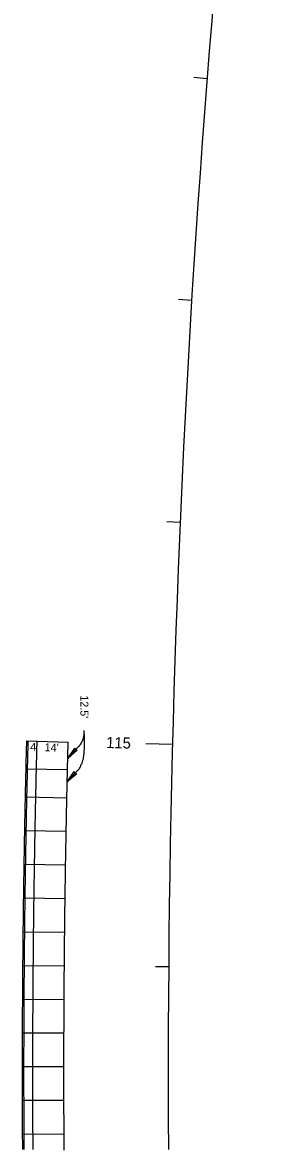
# Model space of a CAD drawing. Extents: x 2145147 to 2158018, y 137519 to 148068.
# Drawn here: x 2150739 to 2150856, y 146337 to 146844 of the extents above; entities that cross this region are included whole.
import ezdxf

# ---------------------------------------------------------------- set-up
doc = ezdxf.new("R2010")
doc.units = 0
for name, color, linetype in [('EX_Align', 7, 'Continuous'), ('EX_Align_Sta', 7, 'Continuous'), ('PR_Dimensions', 7, 'Continuous'), ('PR_Joint_Contraction', 7, 'Continuous'), ('PR_Joint_Long', 7, 'Continuous'), ('PR_Road_Concrete', 7, 'Continuous')]:
    doc.layers.add(name, color=color, linetype=linetype)

msp = doc.modelspace()

# ---------------------------------------------------------------- linework, layer by layer
at = {"layer": 'EX_Align'}
for points in [[(2150816.02, 146819.16), (2150822, 146818.69)], [(2150809.07, 146719.3), (2150815.06, 146718.94)], [(2150803.87, 146619.33), (2150809.87, 146619.07)], [(2150794.42, 146519.44), (2150806.41, 146519.13)], [(2150798.7, 146419.2), (2150804.7, 146419.15)]]:
    msp.add_lwpolyline(points, dxfattribs=at)
msp.add_arc((2156534.08, 146371.27), 5729.58, 162.772825, 180.344259, dxfattribs=at)
at = {"layer": 'PR_Dimensions'}
for points in [[(2150759.24, 146512.79), (2150762.39, 146517.43), (2150762.56, 146516.5), (2150763.53, 146516.41)], [(2150758.99, 146502.2), (2150762.14, 146506.85), (2150762.31, 146505.92), (2150763.28, 146505.82)]]:
    msp.add_lwpolyline(points, close=True, dxfattribs=at)
for points in [[(2150766.51, 146525.33), (2150766.94, 146514.1), (2150764.48, 146508.01), (2150763.54, 146507.3), (2150758.99, 146502.2)], [(2150766.51, 146525.33), (2150766.6, 146522.27), (2150764.73, 146518.59), (2150763.79, 146517.88), (2150759.24, 146512.79)]]:
    msp.add_open_spline(points, degree=2, dxfattribs=at)
at = {"layer": 'PR_Joint_Contraction'}
for p, q in [((2150740.45, 146508.14), (2150759.12, 146507.7)), ((2150740.17, 146495.5), (2150758.83, 146495.1)), ((2150739.86, 146480.33), (2150758.53, 146479.98)), ((2150739.6, 146465.16), (2150758.26, 146464.86)), ((2150739.37, 146449.99), (2150758.04, 146449.74)), ((2150739.19, 146434.82), (2150757.85, 146434.61)), ((2150739.04, 146419.65), (2150757.71, 146419.49)), ((2150738.93, 146404.48), (2150757.6, 146404.37)), ((2150738.87, 146389.3), (2150757.53, 146389.25)), ((2150738.84, 146374.13), (2150757.5, 146374.12)), ((2150738.85, 146358.96), (2150757.52, 146359)), ((2150738.9, 146343.79), (2150757.57, 146343.88))]:
    msp.add_line(p, q, dxfattribs=at)
at = {"layer": 'PR_Joint_Long'}
for points in [[(2150743.61, 146336.79), (2150743.6, 146337.8), (2150743.6, 146338.81), (2150743.59, 146339.82), (2150743.58, 146340.83), (2150743.58, 146341.84), (2150743.57, 146342.85), (2150743.57, 146342.87), (2150743.57, 146343.86), (2150743.56, 146344.87), (2150743.56, 146345.88), (2150743.56, 146346.89), (2150743.55, 146347.9), (2150743.55, 146348.92), (2150743.54, 146349.93), (2150743.54, 146350.94), (2150743.54, 146351.79), (2150743.54, 146351.95), (2150743.53, 146352.96), (2150743.53, 146353.97), (2150743.53, 146354.98), (2150743.52, 146355.99), (2150743.52, 146357), (2150743.52, 146358.01), (2150743.52, 146359.02), (2150743.52, 146360.03), (2150743.51, 146361.04), (2150743.51, 146362.05), (2150743.51, 146363.06), (2150743.51, 146364.07), (2150743.51, 146365.09), (2150743.51, 146366.1), (2150743.51, 146366.5), (2150743.51, 146367.11), (2150743.51, 146368.12), (2150743.5, 146369.13), (2150743.5, 146370.14), (2150743.5, 146371.15), (2150743.5, 146372.16), (2150743.5, 146373.17), (2150743.5, 146374.18), (2150743.51, 146374.97), (2150743.51, 146375.19), (2150743.51, 146376.2), (2150743.51, 146376.23), (2150743.51, 146377.21), (2150743.51, 146378.22), (2150743.51, 146379.23), (2150743.51, 146380.25), (2150743.51, 146381.26), (2150743.51, 146382.27), (2150743.51, 146382.4), (2150743.52, 146383.28), (2150743.52, 146384.29), (2150743.52, 146385.02), (2150743.52, 146385.3), (2150743.52, 146386.31), (2150743.53, 146387.32), (2150743.53, 146388.33), (2150743.53, 146389.34), (2150743.54, 146390.35), (2150743.54, 146391.36), (2150743.54, 146392.37), (2150743.55, 146393.38), (2150743.55, 146394.39), (2150743.55, 146395.4), (2150743.56, 146396.42), (2150743.56, 146397.43), (2150743.56, 146397.71), (2150743.57, 146398.44), (2150743.57, 146399.45), (2150743.58, 146400.46), (2150743.58, 146401.47), (2150743.59, 146402.48), (2150743.59, 146403.49), (2150743.6, 146404.5), (2150743.61, 146405.51), (2150743.61, 146406.52), (2150743.62, 146407.53), (2150743.62, 146408.54), (2150743.63, 146409.55), (2150743.64, 146410.56), (2150743.64, 146411.57), (2150743.65, 146412.59), (2150743.65, 146413.02), (2150743.66, 146413.6), (2150743.67, 146414.61), (2150743.67, 146415.62), (2150743.68, 146416.63), (2150743.69, 146417.64), (2150743.7, 146418.65), (2150743.71, 146419.66), (2150743.72, 146420.67), (2150743.72, 146421.68), (2150743.73, 146422.69), (2150743.74, 146423.7), (2150743.75, 146424.71), (2150743.76, 146425.72), (2150743.77, 146426.73), (2150743.78, 146427.74), (2150743.79, 146428.33), (2150743.79, 146428.76), (2150743.8, 146429.77), (2150743.81, 146430.78), (2150743.82, 146431.79), (2150743.83, 146432.8), (2150743.84, 146433.81), (2150743.85, 146434.82), (2150743.86, 146435.83), (2150743.88, 146436.84), (2150743.89, 146437.85), (2150743.9, 146438.86), (2150743.91, 146439.87), (2150743.92, 146440.88), (2150743.93, 146441.89), (2150743.95, 146442.9), (2150743.96, 146443.64), (2150743.96, 146443.91), (2150743.97, 146444.72), (2150743.97, 146444.92), (2150743.99, 146445.94), (2150744, 146446.95), (2150744.01, 146447.96), (2150744.03, 146448.97), (2150744.04, 146449.98), (2150744.05, 146450.99), (2150744.07, 146452), (2150744.08, 146453.01), (2150744.1, 146454.02), (2150744.11, 146455.03), (2150744.12, 146456.04), (2150744.14, 146457.05), (2150744.15, 146458.06), (2150744.17, 146458.95), (2150744.17, 146459.07), (2150744.19, 146460.08), (2150744.2, 146461.09), (2150744.22, 146462.1), (2150744.23, 146463.11), (2150744.25, 146464.12), (2150744.27, 146465.14), (2150744.28, 146466.15), (2150744.28, 146466.33), (2150744.3, 146467.16), (2150744.32, 146468.17), (2150744.33, 146469.18), (2150744.35, 146470.19), (2150744.37, 146471.2), (2150744.38, 146472.21), (2150744.4, 146473.22), (2150744.42, 146474.23), (2150744.42, 146474.25), (2150744.44, 146475.24), (2150744.46, 146476.25), (2150744.47, 146477.26), (2150744.49, 146478.27), (2150744.51, 146479.28), (2150744.53, 146480.29), (2150744.55, 146481.3), (2150744.57, 146482.31), (2150744.59, 146483.32), (2150744.61, 146484.33), (2150744.63, 146485.35), (2150744.65, 146486.36), (2150744.67, 146487.37), (2150744.69, 146488.38), (2150744.71, 146489.39), (2150744.71, 146489.56), (2150744.73, 146490.4), (2150744.75, 146491.41), (2150744.76, 146491.89), (2150744.77, 146492.42), (2150744.79, 146493.43), (2150744.81, 146494.44), (2150744.84, 146495.45), (2150744.86, 146496.46), (2150744.88, 146497.47), (2150744.9, 146498.48), (2150744.92, 146499.49), (2150744.95, 146500.5), (2150744.97, 146501.51), (2150744.99, 146502.52), (2150745.01, 146503.53), (2150745.04, 146504.54), (2150745.05, 146504.86), (2150745.06, 146505.55), (2150745.09, 146506.56), (2150745.11, 146507.49), (2150745.11, 146507.57), (2150745.13, 146508.58), (2150745.16, 146509.59), (2150745.18, 146510.61), (2150745.21, 146511.62), (2150745.23, 146512.63), (2150745.25, 146513.64), (2150745.28, 146514.65), (2150745.3, 146515.66), (2150745.33, 146516.67), (2150745.36, 146517.68), (2150745.38, 146518.69), (2150745.41, 146519.7), (2150745.42, 146520.17), (2150745.43, 146520.49)], [(2150757.61, 146336.56), (2150757.61, 146336.87), (2150757.6, 146337.88), (2150757.6, 146338.89), (2150757.59, 146339.9), (2150757.58, 146340.9), (2150757.58, 146341.91), (2150757.57, 146342.92), (2150757.57, 146342.94), (2150757.57, 146343.93), (2150757.56, 146344.94), (2150757.56, 146345.94), (2150757.56, 146346.95), (2150757.55, 146347.96), (2150757.55, 146348.97), (2150757.54, 146349.98), (2150757.54, 146350.99), (2150757.54, 146351.83), (2150757.54, 146351.99), (2150757.53, 146353), (2150757.53, 146354.01), (2150757.53, 146355.02), (2150757.52, 146356.03), (2150757.52, 146357.03), (2150757.52, 146358.04), (2150757.52, 146359.05), (2150757.52, 146360.06), (2150757.51, 146361.07), (2150757.51, 146362.08), (2150757.51, 146363.08), (2150757.51, 146364.09), (2150757.51, 146365.1), (2150757.51, 146366.11), (2150757.51, 146366.51), (2150757.51, 146367.1), (2150757.51, 146367.12), (2150757.51, 146368.13), (2150757.5, 146369.13), (2150757.5, 146370.14), (2150757.5, 146371.15), (2150757.5, 146372.16), (2150757.5, 146373.17), (2150757.5, 146374.17), (2150757.51, 146374.96), (2150757.51, 146375.18), (2150757.51, 146376.19), (2150757.51, 146376.22), (2150757.51, 146377.2), (2150757.51, 146378.21), (2150757.51, 146379.22), (2150757.51, 146380.22), (2150757.51, 146381.23), (2150757.51, 146382.24), (2150757.51, 146382.38), (2150757.52, 146383.25), (2150757.52, 146384.26), (2150757.52, 146384.99), (2150757.52, 146385.26), (2150757.52, 146386.27), (2150757.53, 146387.28), (2150757.53, 146388.29), (2150757.53, 146389.3), (2150757.54, 146390.31), (2150757.54, 146391.31), (2150757.54, 146392.32), (2150757.55, 146393.33), (2150757.55, 146394.34), (2150757.55, 146395.35), (2150757.56, 146396.35), (2150757.56, 146397.36), (2150757.56, 146397.65), (2150757.57, 146398.37), (2150757.57, 146399.38), (2150757.58, 146400.39), (2150757.58, 146401.4), (2150757.59, 146402.4), (2150757.59, 146403.41), (2150757.6, 146404.42), (2150757.61, 146405.43), (2150757.61, 146406.44), (2150757.62, 146407.43), (2150757.62, 146407.44), (2150757.62, 146408.45), (2150757.63, 146409.46), (2150757.64, 146410.47), (2150757.64, 146411.48), (2150757.65, 146412.49), (2150757.65, 146412.92), (2150757.66, 146413.49), (2150757.67, 146414.5), (2150757.67, 146415.51), (2150757.68, 146416.52), (2150757.69, 146417.53), (2150757.7, 146418.53), (2150757.71, 146419.54), (2150757.71, 146420.55), (2150757.72, 146421.56), (2150757.73, 146422.57), (2150757.74, 146423.58), (2150757.75, 146424.58), (2150757.76, 146425.59), (2150757.77, 146426.6), (2150757.78, 146427.61), (2150757.78, 146428.19), (2150757.79, 146428.62), (2150757.8, 146429.62), (2150757.81, 146430.63), (2150757.82, 146431.64), (2150757.83, 146432.65), (2150757.84, 146433.66), (2150757.85, 146434.67), (2150757.86, 146435.67), (2150757.87, 146436.68), (2150757.89, 146437.69), (2150757.9, 146438.7), (2150757.91, 146439.71), (2150757.92, 146440.71), (2150757.93, 146441.72), (2150757.95, 146442.73), (2150757.96, 146443.46), (2150757.96, 146443.74), (2150757.97, 146444.55), (2150757.97, 146444.75), (2150757.98, 146445.75), (2150758, 146446.76), (2150758.01, 146447.77), (2150758.02, 146448.78), (2150758.04, 146449.79), (2150758.05, 146450.8), (2150758.07, 146451.8), (2150758.08, 146452.81), (2150758.09, 146453.82), (2150758.11, 146454.83), (2150758.12, 146455.84), (2150758.14, 146456.84), (2150758.15, 146457.85), (2150758.17, 146458.73), (2150758.17, 146458.86), (2150758.18, 146459.87), (2150758.2, 146460.88), (2150758.22, 146461.88), (2150758.23, 146462.89), (2150758.25, 146463.9), (2150758.26, 146464.91), (2150758.28, 146465.92), (2150758.28, 146466.1), (2150758.3, 146466.92), (2150758.31, 146467.93), (2150758.33, 146468.94), (2150758.35, 146469.95), (2150758.36, 146470.96), (2150758.38, 146471.96), (2150758.4, 146472.97), (2150758.42, 146473.98), (2150758.42, 146474), (2150758.44, 146474.99), (2150758.45, 146476), (2150758.47, 146477.01), (2150758.49, 146478.01), (2150758.51, 146479.02), (2150758.53, 146480.03), (2150758.55, 146481.04), (2150758.57, 146482.05), (2150758.59, 146483.05), (2150758.61, 146484.06), (2150758.63, 146485.07), (2150758.65, 146486.08), (2150758.67, 146487.09), (2150758.69, 146488.09), (2150758.71, 146489.1), (2150758.71, 146489.27), (2150758.73, 146490.11), (2150758.75, 146491.12), (2150758.76, 146491.6), (2150758.77, 146492.13), (2150758.79, 146493.13), (2150758.81, 146494.14), (2150758.83, 146495.15), (2150758.85, 146496.16), (2150758.88, 146497.17), (2150758.9, 146498.17), (2150758.92, 146499.18), (2150758.94, 146500.19), (2150758.97, 146501.2), (2150758.99, 146502.2), (2150759.01, 146503.21), (2150759.03, 146504.22), (2150759.04, 146504.54), (2150759.06, 146505.23), (2150759.08, 146506.24), (2150759.1, 146507.16), (2150759.1, 146507.24), (2150759.13, 146508.25), (2150759.15, 146509.26), (2150759.18, 146510.27), (2150759.2, 146511.28), (2150759.23, 146512.28), (2150759.25, 146513.29), (2150759.28, 146514.3), (2150759.3, 146515.31), (2150759.33, 146516.32), (2150759.35, 146517.32), (2150759.38, 146518.33), (2150759.4, 146519.34), (2150759.41, 146519.81), (2150759.42, 146520.13)]]:
    msp.add_lwpolyline(points, dxfattribs=at)
at = {"layer": 'PR_Road_Concrete'}
msp.add_line((2150740.76, 146520.61), (2150759.42, 146520.13), dxfattribs=at)
for points in [[(2150738.94, 146336.76), (2150738.93, 146337.77), (2150738.93, 146338.78), (2150738.92, 146339.79), (2150738.92, 146340.81), (2150738.91, 146341.82), (2150738.91, 146342.83), (2150738.91, 146342.85), (2150738.9, 146343.84), (2150738.9, 146344.85), (2150738.89, 146345.86), (2150738.89, 146346.87), (2150738.88, 146347.89), (2150738.88, 146348.9), (2150738.88, 146349.91), (2150738.87, 146350.92), (2150738.87, 146351.77), (2150738.87, 146351.93), (2150738.87, 146352.94), (2150738.86, 146353.95), (2150738.86, 146354.97), (2150738.86, 146355.98), (2150738.86, 146356.99), (2150738.85, 146358), (2150738.85, 146359.01), (2150738.85, 146360.02), (2150738.85, 146361.03), (2150738.84, 146362.05), (2150738.84, 146363.06), (2150738.84, 146364.07), (2150738.84, 146365.08), (2150738.84, 146366.09), (2150738.84, 146366.49), (2150738.84, 146367.09), (2150738.84, 146367.1), (2150738.84, 146368.11), (2150738.84, 146369.13), (2150738.84, 146370.14), (2150738.84, 146371.15), (2150738.84, 146372.16), (2150738.84, 146373.17), (2150738.84, 146374.18), (2150738.84, 146374.97), (2150738.84, 146375.2), (2150738.84, 146376.21), (2150738.84, 146376.24), (2150738.84, 146377.22), (2150738.84, 146378.23), (2150738.84, 146379.24), (2150738.84, 146380.25), (2150738.85, 146381.26), (2150738.85, 146382.28), (2150738.85, 146382.41), (2150738.85, 146383.29), (2150738.85, 146384.3), (2150738.85, 146385.03), (2150738.85, 146385.31), (2150738.86, 146386.32), (2150738.86, 146387.33), (2150738.86, 146388.34), (2150738.87, 146389.36), (2150738.87, 146390.37), (2150738.87, 146391.38), (2150738.88, 146392.39), (2150738.88, 146393.4), (2150738.88, 146394.41), (2150738.89, 146395.42), (2150738.89, 146396.44), (2150738.9, 146397.45), (2150738.9, 146397.73), (2150738.9, 146398.46), (2150738.91, 146399.47), (2150738.91, 146400.48), (2150738.92, 146401.49), (2150738.92, 146402.5), (2150738.93, 146403.52), (2150738.93, 146404.53), (2150738.94, 146405.54), (2150738.94, 146406.55), (2150738.95, 146407.55), (2150738.95, 146407.56), (2150738.96, 146408.57), (2150738.96, 146409.58), (2150738.97, 146410.6), (2150738.98, 146411.61), (2150738.99, 146412.62), (2150738.99, 146413.05), (2150738.99, 146413.63), (2150739, 146414.64), (2150739.01, 146415.65), (2150739.02, 146416.66), (2150739.02, 146417.68), (2150739.03, 146418.69), (2150739.04, 146419.7), (2150739.05, 146420.71), (2150739.06, 146421.72), (2150739.07, 146422.73), (2150739.08, 146423.74), (2150739.08, 146424.76), (2150739.09, 146425.77), (2150739.1, 146426.78), (2150739.11, 146427.79), (2150739.12, 146428.38), (2150739.12, 146428.8), (2150739.13, 146429.81), (2150739.14, 146430.82), (2150739.15, 146431.84), (2150739.16, 146432.85), (2150739.18, 146433.86), (2150739.19, 146434.87), (2150739.2, 146435.88), (2150739.21, 146436.89), (2150739.22, 146437.9), (2150739.23, 146438.92), (2150739.24, 146439.93), (2150739.26, 146440.94), (2150739.27, 146441.95), (2150739.28, 146442.96), (2150739.29, 146443.7), (2150739.29, 146443.97), (2150739.3, 146444.78), (2150739.31, 146444.98), (2150739.32, 146446), (2150739.33, 146447.01), (2150739.35, 146448.02), (2150739.36, 146449.03), (2150739.37, 146450.04), (2150739.39, 146451.05), (2150739.4, 146452.06), (2150739.42, 146453.07), (2150739.43, 146454.09), (2150739.44, 146455.1), (2150739.46, 146456.11), (2150739.47, 146457.12), (2150739.49, 146458.13), (2150739.5, 146459.02), (2150739.5, 146459.14), (2150739.52, 146460.15), (2150739.53, 146461.17), (2150739.55, 146462.18), (2150739.57, 146463.19), (2150739.58, 146464.2), (2150739.6, 146465.21), (2150739.62, 146466.22), (2150739.62, 146466.41), (2150739.63, 146467.23), (2150739.65, 146468.24), (2150739.67, 146469.26), (2150739.68, 146470.27), (2150739.7, 146471.28), (2150739.72, 146472.29), (2150739.74, 146473.3), (2150739.75, 146474.31), (2150739.75, 146474.34), (2150739.77, 146475.32), (2150739.79, 146476.34), (2150739.81, 146477.35), (2150739.83, 146478.36), (2150739.85, 146479.37), (2150739.86, 146480.38), (2150739.88, 146481.39), (2150739.9, 146482.4), (2150739.92, 146483.41), (2150739.94, 146484.43), (2150739.96, 146485.44), (2150739.98, 146486.45), (2150740, 146487.46), (2150740.02, 146488.47), (2150740.04, 146489.48), (2150740.05, 146489.65), (2150740.06, 146490.49), (2150740.09, 146491.5), (2150740.1, 146491.99), (2150740.11, 146492.52), (2150740.13, 146493.53), (2150740.15, 146494.54), (2150740.17, 146495.55), (2150740.19, 146496.56), (2150740.21, 146497.57), (2150740.24, 146498.58), (2150740.26, 146499.59), (2150740.28, 146500.61), (2150740.3, 146501.62), (2150740.33, 146502.63), (2150740.35, 146503.64), (2150740.37, 146504.65), (2150740.38, 146504.97), (2150740.4, 146505.66), (2150740.42, 146506.67), (2150740.44, 146507.6), (2150740.44, 146507.68), (2150740.47, 146508.7), (2150740.49, 146509.71), (2150740.52, 146510.72), (2150740.54, 146511.73), (2150740.56, 146512.74), (2150740.59, 146513.75), (2150740.61, 146514.76), (2150740.64, 146515.77), (2150740.66, 146516.78), (2150740.69, 146517.8), (2150740.72, 146518.81), (2150740.74, 146519.82), (2150740.75, 146520.29), (2150740.76, 146520.61)], [(2150739.61, 146336.76), (2150739.6, 146337.78), (2150739.6, 146338.79), (2150739.59, 146339.8), (2150739.58, 146340.81), (2150739.58, 146341.82), (2150739.57, 146342.83), (2150739.57, 146342.85), (2150739.57, 146343.84), (2150739.56, 146344.85), (2150739.56, 146345.87), (2150739.56, 146346.88), (2150739.55, 146347.89), (2150739.55, 146348.9), (2150739.54, 146349.91), (2150739.54, 146350.92), (2150739.54, 146351.77), (2150739.54, 146351.93), (2150739.53, 146352.95), (2150739.53, 146353.96), (2150739.53, 146354.97), (2150739.52, 146355.98), (2150739.52, 146356.99), (2150739.52, 146358), (2150739.52, 146359.01), (2150739.52, 146360.02), (2150739.51, 146361.04), (2150739.51, 146362.05), (2150739.51, 146363.06), (2150739.51, 146364.07), (2150739.51, 146365.08), (2150739.51, 146366.09), (2150739.51, 146366.49), (2150739.51, 146367.09), (2150739.51, 146367.1), (2150739.51, 146368.12), (2150739.5, 146369.13), (2150739.5, 146370.14), (2150739.5, 146371.15), (2150739.5, 146372.16), (2150739.5, 146373.17), (2150739.5, 146374.18), (2150739.51, 146374.97), (2150739.51, 146375.19), (2150739.51, 146376.21), (2150739.51, 146376.24), (2150739.51, 146377.22), (2150739.51, 146378.23), (2150739.51, 146379.24), (2150739.51, 146380.25), (2150739.51, 146381.26), (2150739.51, 146382.27), (2150739.51, 146382.41), (2150739.52, 146383.29), (2150739.52, 146384.3), (2150739.52, 146385.03), (2150739.52, 146385.31), (2150739.52, 146386.32), (2150739.53, 146387.33), (2150739.53, 146388.34), (2150739.53, 146389.35), (2150739.54, 146390.36), (2150739.54, 146391.38), (2150739.54, 146392.39), (2150739.55, 146393.4), (2150739.55, 146394.41), (2150739.55, 146395.42), (2150739.56, 146396.43), (2150739.56, 146397.44), (2150739.56, 146397.73), (2150739.57, 146398.46), (2150739.57, 146399.47), (2150739.58, 146400.48), (2150739.58, 146401.49), (2150739.59, 146402.5), (2150739.59, 146403.51), (2150739.6, 146404.52), (2150739.61, 146405.53), (2150739.61, 146406.55), (2150739.62, 146407.55), (2150739.62, 146407.56), (2150739.62, 146408.57), (2150739.63, 146409.58), (2150739.64, 146410.59), (2150739.64, 146411.6), (2150739.65, 146412.61), (2150739.65, 146413.05), (2150739.66, 146413.63), (2150739.67, 146414.64), (2150739.67, 146415.65), (2150739.68, 146416.66), (2150739.69, 146417.67), (2150739.7, 146418.68), (2150739.71, 146419.69), (2150739.72, 146420.7), (2150739.72, 146421.72), (2150739.73, 146422.73), (2150739.74, 146423.74), (2150739.75, 146424.75), (2150739.76, 146425.76), (2150739.77, 146426.77), (2150739.78, 146427.78), (2150739.79, 146428.37), (2150739.79, 146428.79), (2150739.8, 146429.81), (2150739.81, 146430.82), (2150739.82, 146431.83), (2150739.83, 146432.84), (2150739.84, 146433.85), (2150739.85, 146434.86), (2150739.86, 146435.87), (2150739.88, 146436.89), (2150739.89, 146437.9), (2150739.9, 146438.91), (2150739.91, 146439.92), (2150739.92, 146440.93), (2150739.94, 146441.94), (2150739.95, 146442.95), (2150739.96, 146443.69), (2150739.96, 146443.96), (2150739.97, 146444.77), (2150739.97, 146444.98), (2150739.99, 146445.99), (2150740, 146447), (2150740.01, 146448.01), (2150740.03, 146449.02), (2150740.04, 146450.03), (2150740.05, 146451.04), (2150740.07, 146452.05), (2150740.08, 146453.07), (2150740.1, 146454.08), (2150740.11, 146455.09), (2150740.13, 146456.1), (2150740.14, 146457.11), (2150740.16, 146458.12), (2150740.17, 146459.01), (2150740.17, 146459.13), (2150740.19, 146460.14), (2150740.2, 146461.16), (2150740.22, 146462.17), (2150740.23, 146463.18), (2150740.25, 146464.19), (2150740.27, 146465.2), (2150740.28, 146466.21), (2150740.29, 146466.39), (2150740.3, 146467.22), (2150740.32, 146468.23), (2150740.33, 146469.25), (2150740.35, 146470.26), (2150740.37, 146471.27), (2150740.38, 146472.28), (2150740.4, 146473.29), (2150740.42, 146474.3), (2150740.42, 146474.32), (2150740.44, 146475.31), (2150740.46, 146476.32), (2150740.48, 146477.33), (2150740.49, 146478.35), (2150740.51, 146479.36), (2150740.53, 146480.37), (2150740.55, 146481.38), (2150740.57, 146482.39), (2150740.59, 146483.4), (2150740.61, 146484.41), (2150740.63, 146485.42), (2150740.65, 146486.43), (2150740.67, 146487.45), (2150740.69, 146488.46), (2150740.71, 146489.47), (2150740.71, 146489.64), (2150740.73, 146490.48), (2150740.75, 146491.49), (2150740.76, 146491.97), (2150740.77, 146492.5), (2150740.79, 146493.51), (2150740.82, 146494.52), (2150740.84, 146495.54), (2150740.86, 146496.55), (2150740.88, 146497.56), (2150740.9, 146498.57), (2150740.93, 146499.58), (2150740.95, 146500.59), (2150740.97, 146501.6), (2150740.99, 146502.61), (2150741.02, 146503.62), (2150741.04, 146504.63), (2150741.05, 146504.96), (2150741.06, 146505.65), (2150741.09, 146506.66), (2150741.11, 146507.58), (2150741.11, 146507.67), (2150741.13, 146508.68), (2150741.16, 146509.69), (2150741.18, 146510.7), (2150741.21, 146511.71), (2150741.23, 146512.72), (2150741.26, 146513.73), (2150741.28, 146514.75), (2150741.31, 146515.76), (2150741.33, 146516.77), (2150741.36, 146517.78), (2150741.38, 146518.79), (2150741.41, 146519.8), (2150741.42, 146520.27), (2150741.43, 146520.59)]]:
    msp.add_lwpolyline(points, dxfattribs=at)

# ---------------------------------------------------------------- texts
at = {"layer": 'EX_Align_Sta'}
msp.add_text('115', height=5, rotation=358.5212, dxfattribs=at).set_placement((2150776.47, 146517.44))
at = {"layer": 'PR_Dimensions'}
for s, rotation, p in [("12.5'", 269.9996, (2150764.93, 146541.12)), ("4'", 358.2838, (2150742.29, 146516.21)), ("14'", 358.2838, (2150748.81, 146515.99))]:
    msp.add_text(s, height=3.6, rotation=rotation, dxfattribs=at).set_placement(p)

doc.saveas('drawing.dxf')
